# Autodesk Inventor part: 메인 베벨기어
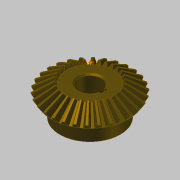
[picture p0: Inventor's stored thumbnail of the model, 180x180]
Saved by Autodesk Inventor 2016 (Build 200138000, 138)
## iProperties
Created: 2014-10
Part Number: 메인 베벨기어
Material: 강철, 탄소
Document SubType Name: Modeling
Designer: KYOUNG IL JANG
Categories: <?xml version="1.0" encoding="UTF-16"?> <MemberInstance><Categories><FamilyTemplate><FamilyTemplateParameter ValueType="xs:double" Id="1" ObjectReferenceKey="da
Mass: 269.583 g
Surface Area: 108.837 cm^2
Volume: 34.2981 cm^3
Density: 7.86 g/cm^3
Appearance: 얼룩무늬
CustomPartVersion: 1
Revision Number: 1
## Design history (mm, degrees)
node "맨 위 점"
node "메쉬 평면2"
sketch "톱니 본체 스케치"
  geometry: L1 (0, 0)-(28.669, -21.997); L2 (28.669, -21.997)-(31.109, -18.336); L3 (31.109, -18.336)-(0, 0); L4 (30, -20)-(0, 0); L5 (17.219, -13.212)-(18.685, -11.013); L6 (28.669, -21.997)-(17.219, -13.212); L7 (31.109, -18.336)-(18.685, -11.013); L8 (0, -39.387)-(0, 6.564) reference; L9 (0, -20)-(31.109, -20)
  constraints: 16 end point, 4 point on line, 3 perpendicular, 2 collinear, 1 horizontal alignment, 1 vertical alignment
  dimensions: "d0" = 60 diameter of L4.start L8 (= da_de); "d1" = 57.33744 diameter of L1.end L8 (= da_dfe); "d2" = 62.2188 diameter of L2.end L8 (= da_dae); "d3" = 14.4 distance between parallel lines of L2 L5 (= da_b); "d4" = 18.3359 vertical distance of L2.end L1.start (= da_ve)
revolve "톱니 본체" sketch "톱니 본체 스케치" stored, may be unused: angle "d5" = 90 deg
node "시작점"
node "톱니 평면"
sketch "시작 스케치"
  geometry: L1 (0, -23.505)-(0, 10.645) reference; L2 (-0.709, -2.928)-(0.709, -2.928); A1 r 19.188 centre (-19.457, -7.014) between (-0.709, -2.928) and (-3.232, 3.229); A2 r 19.188 centre (19.457, -7.014) between (3.232, 3.229) and (0.709, -2.928); A3 r 57.403 centre (0, -54.083) between (3.232, 3.229) and (-3.232, 3.229); 1 further point
  constraints: 6 point on circle, 3 centre point, 3 symmetric about line, 2 end point, 1 coincident, 1 perpendicular, 1 other
  dimensions: "d7" = 19.18795 radius of A1 (= fd_rr); "d8" = 19.45712 horizontal distance of point (0, -54.083) A1.centre (= fd_x); "d9" = 47.06905 vertical distance of point (0, -54.083) A1.centre (= fd_y); "d57" = 57.40327 radius of A3 (= 0.5 x fd_dva + 0.3 x da_he); "d58" = 51.15527 distance from line of A3.centre L2 (= 0.5 x fd_dva - 1.12 x da_he)
node "끝점"
  node "끝 평면"
sketch "3D 스케치 오른쪽"
  node "Helical Curve Right" dims "d65" = 229.90621 (computed from da_dm, da_delta, da_beta), "d66" = 31.5, "d67" = 60 (= da_de), "d68" = -9.82794 (= -da_delta), "d69" = 8.10972 (computed from fd_loft, da_delta)
node "끝 평면 오른쪽"
sketch "끝 스케치 오른쪽"
  geometry: L1 (0, -41.54)-(0, 13.178) reference; L2 (-0.422, -1.69)-(0.422, -1.69); A1 r 11.427 centre (-11.587, -4.123) between (-0.422, -1.69) and (-1.925, 1.977); A2 r 11.427 centre (11.587, -4.123) between (1.925, 1.977) and (0.422, -1.69); A3 r 34.184 centre (0, -32.153) between (1.925, 1.977) and (-1.925, 1.977); 1 further point
  constraints: 6 point on circle, 3 centre point, 3 symmetric about line, 2 end point, 1 coincident, 1 perpendicular, 1 other
  dimensions: "d70" = 11.58699 horizontal distance of A3.centre A1.centre (computed from fd_x, fd_ratio); "d71" = 28.03028 vertical distance of point (0, -32.153) A1.centre (computed from fd_y, fd_ratio); "d72" = 11.4267 radius of A1 (computed from fd_rr, fd_ratio); "d73" = 30.46369 distance from line of point (0, -32.153) L2 (computed from d58, fd_ratio); "d74" = 34.18446 radius of A3 (computed from d57, fd_ratio)
feature "로프트 오른쪽" sketch "끝 스케치 오른쪽" dims "d75" = 0, "d77" = 0, "d79" = 0, "d80" = 90 deg, "d85" = 20, "d92" = 90 deg, "d93" = 90 deg, "da_teethtype" = 0 [user parameter]
sketch "3D 스케치 왼쪽"
  node "Helical Curve Left" dims "d26" = 229.90621 (computed from da_dm, da_delta, da_beta), "d27" = 8.10972 (computed from fd_loft, da_delta), "d28" = 60 (= da_de), "d29" = -9.82794 (= -da_delta)
node "끝 평면 왼쪽"
sketch "끝 스케치 왼쪽" dims "d56" = 10.3728 (derived)
  geometry: L1 (0, -43.753)-(0, 15.405) reference; L2 (-0.422, -1.678)-(0.422, -1.678); A1 r 11.427 centre (-11.587, -4.111) between (-0.422, -1.678) and (-1.925, 1.988); A2 r 11.427 centre (11.587, -4.111) between (1.925, 1.988) and (0.422, -1.678); A3 r 34.184 centre (0, -32.142) between (1.925, 1.988) and (-1.925, 1.988); 2 further points; 1 other entity
  constraints: 6 point on circle, 3 centre point, 3 symmetric about line, 2 end point, 1 coincident, 2 other
  dimensions: "d30" = 11.4267 radius of A1 (computed from fd_rr, fd_ratio); "d31" = 11.58699 horizontal distance of point (0, -32.142) A1.centre (computed from fd_x, fd_ratio); "d32" = 28.03028 vertical distance of A1.centre point (0, -32.142) (computed from fd_y, fd_ratio); "d61" = 34.18446 radius of A3 (computed from d57, fd_ratio); "d62" = 30.46369 distance from line of point (0, -32.142) L2 (computed from d58, fd_ratio)
feature "로프트 왼쪽" sketch "끝 스케치 왼쪽" dims "d35" = 0, "d37" = 0, "d39" = 0, "d40" = 90 deg, "d84" = 10, "d90" = 90 deg, "d91" = 90 deg, "da_teethtype" = 0 [user parameter]
sketch "본체 스케치"
  geometry: L1 (0, -35.038)-(0, -19.531) reference; L2 (28.669, -21.997)-(17.219, -13.212) reference; L3 (17.219, -13.212)-(0, -13.212); L4 (28.669, -21.997)-(0, -21.997)
  constraints: 4 end point, 2 perpendicular, 2 point on line
revolve "본체 고정" sketch "본체 스케치" stored, may be unused: angle "d46" = 90 deg
feature "피치 지름" dims angle "d47" = 90 deg
sketch "스케치8"
  geometry: C1 r 22.5 at (0, 0); 1 further point
  constraints: 1 centre point, 1 coincident
  dimensions: "d94" = 45 diameter of C1
extrude "돌출1" join sketch "스케치8" distance "d95" = 13; taper "d96" = 0 deg
sketch "스케치9"
  geometry: 1 further point
hole "구멍1" sketch "스케치9" at (0, 0) diameter "d97" = 17; stored, may be unused: countersink angle "d101" = 90 deg, drill point angle "d103" = 118 deg; dims "d98" = 6, "d99" = 4, "d100" = 2, "d102" = 8
sketch "스케치10"
  geometry: L1 (8.124, 2.5)-(10.8, 2.5); L2 (10.8, 2.5)-(10.8, -2.5); L3 (10.8, -2.5)-(8.124, -2.5); A1 r 8.5 centre (0, 0) between (8.124, 2.5) and (8.124, -2.5) reference; 1 further point
  constraints: 6 end point, 2 parallel, 2 point on circle, 1 horizontal, 1 perpendicular
  dimensions: "d104" = 5 distance of L1.end L2.end; "d112" = 19.3 dimension on A1 L2
extrude "돌출2" cut sketch "스케치10" stored distance "d106" = 10; taper "d107" = 0 deg
chamfer "모따기1" distance "d108" = 1; stored, may be unused: second distance "d109" = 2, angle "d110" = 45 deg
fillet "모깎기1" dims "d111" = 2
body "Solid1"
feature "로프트" dims "d17" = 0, "d18" = 90 deg, "d19" = 0, "d20" = 90 deg, "d89" = 0, "da_teethtype" = 0 [user parameter]
pattern_circular "원형 패턴" dims angle "d22" = 360 deg, "d88" = 0, "da_teethtype" = 0 [user parameter]
pattern_circular "원형 패턴 오른쪽" dims angle "d82" = 360 deg, "da_teethtype" = 0 [user parameter]
pattern_circular "원형 패턴 왼쪽" dims angle "d42" = 360 deg, "da_teethtype" = 0 [user parameter]
sketch "끝 스케치"
  geometry: L1 (0, -15.359)-(0, 6.983) reference; L2 (-0.422, -1.69)-(0.422, -1.69); A1 r 11.427 centre (-11.587, -4.123) between (-0.422, -1.69) and (-1.925, 1.977); A2 r 11.427 centre (11.587, -4.123) between (1.925, 1.977) and (0.422, -1.69); A3 r 34.184 centre (0, -32.153) between (1.925, 1.977) and (-1.925, 1.977); 1 further point
  constraints: 6 point on circle, 3 centre point, 3 symmetric about line, 2 end point, 1 coincident, 1 other
  dimensions: "d12" = 11.4267 radius of A1 (computed from fd_rr, fd_ratio); "d15" = 11.58699 horizontal distance of A1.centre point (0, -32.153) (computed from fd_x, fd_ratio); "d16" = 28.03028 vertical distance of A1.centre point (0, -32.153) (computed from fd_y, fd_ratio); "d59" = 34.18446 radius of A3 (computed from d57, fd_ratio); "d60" = 30.46369 distance from line of A3.centre L2 (computed from d58, fd_ratio)
sketch "Sketch6"
  geometry: L1 (30, -20)-(0, 0) reference; L2 (0, -37.8)-(0, 6.3) reference
body "Srf1"
other parameters: "da_b" = 14.4 [user parameter; used in 2 equation terms], "da_de" = 60 [user parameter; used in 4 equation terms], "da_dae" = 62.2188 [user parameter; used in 2 equation terms], "da_dfe" = 57.33744 [user parameter; used in 1 equation term], "da_le" = 36.05551 [user parameter; used in 1 equation term], "da_omega" = 90 deg [user parameter; used in 1 equation term], "da_beta" = 0 [user parameter; used in 2 equation terms], "da_delta" = 9.82794 [user parameter; used in 8 equation terms], "da_alpha" = 20 deg [user parameter; used in 2 equation terms], "da_he" = 4.4 [user parameter; used in 4 equation terms], "da_ve" = 18.3359 [user parameter; used in 1 equation term], "fd_dv" = 108.16654 (computed from da_de, da_delta) [user parameter; used in 1 equation term], "fd_dva" = 112.16654 (computed from da_dae, da_delta) [user parameter; used in 3 equation terms], "fd_dvb" = 101.6433 (computed from fd_dv, da_alpha) [user parameter; used in 2 equation terms], "da_zv" = 540.83269 [user parameter; used in 1 equation term], "fd_loft" = 14.62 (= da_b + 0.05 x da_he) [user parameter; used in 4 equation terms], "fd_ratio" = 5.95514 (computed from da_le, fd_loft) [user parameter; used in 15 equation terms], "fd_rr" = 19.18795 (computed from fd_dd, fd_dvb) [user parameter; used in 6 equation terms], "fd_angle" = 0.29367 (computed from da_zv) [user parameter; used in 4 equation terms], "fd_x1" = 1.58802 (computed from da_dvw, fd_angle) [user parameter; used in 1 equation term], "fd_y1" = 54.05995 (computed from da_dvw, fd_angle) [user parameter; used in 1 equation term], "fd_x2" = 17.8691 (computed from fd_rr, fd_angle2, fd_angle) [user parameter; used in 1 equation term], "fd_y2" = 6.9909 (computed from fd_rr, fd_angle2, fd_angle) [user parameter; used in 1 equation term], "fd_x" = 19.45712 (= fd_x1 + fd_x2) [user parameter; used in 4 equation terms], "fd_y" = 47.06905 (= fd_y1 - fd_y2) [user parameter; used in 4 equation terms], "fd_angle2" = 3.43555 (computed from fd_dvb, fd_dd, da_alpha) [user parameter; used in 2 equation terms], "fd_dd" = 108.64654 (= fd_dva - 0.8 x da_he) [user parameter; used in 2 equation terms], "da_dvw" = 108.16654 [user parameter; used in 2 equation terms], "d11" = 14.62 (= fd_loft), "da_dm" = 48.01848 [user parameter; used in 2 equation terms], "da_x" = 0 [user parameter], "da_m" = 2 [user parameter], "d48" = 0, "d49" = 0, "d50" = 90 deg (= da_omega), "d51" = 6 deg (computed from da_z), "d52" = 0, "d53" = 0, "d54" = 0
